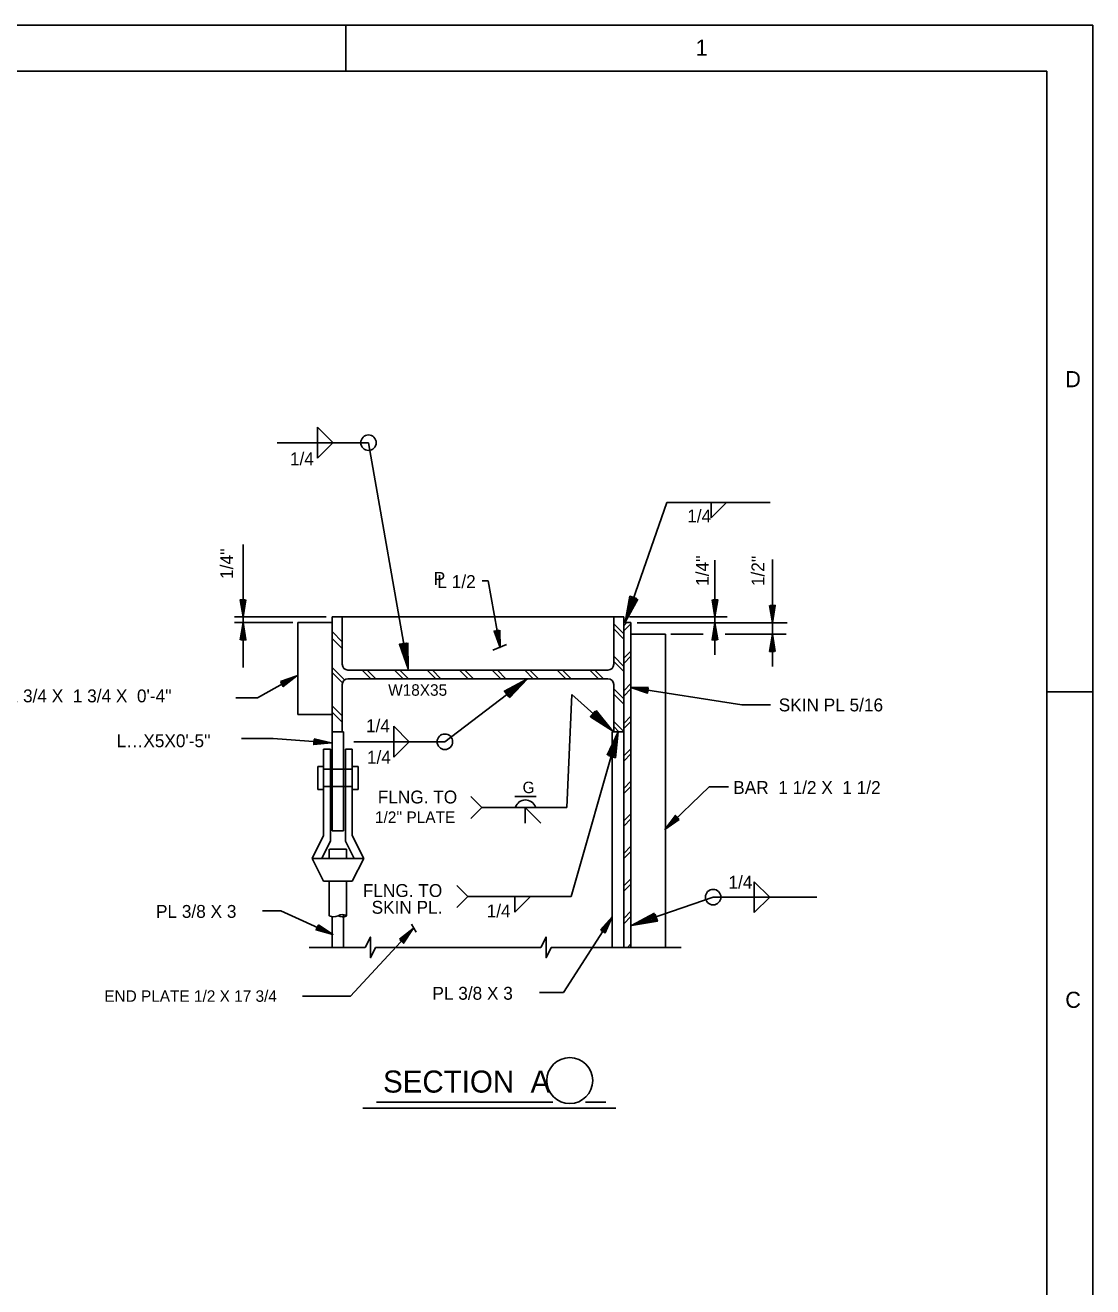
# Model space of a CAD drawing. Extents: x 0 to 13.3, y 0 to 9.3.
# Drawn here: x 9.463 to 13.333, y 4.76 to 9.333 of the extents above; entities that cross this region are included whole.
import ezdxf

# ---------------------------------------------------------------- set-up
doc = ezdxf.new("R2010")
doc.units = 0
for name, color, linetype in [('Level 1', 7, 'Continuous'), ('Level 10', 7, 'Continuous'), ('Level 13', 7, 'Continuous'), ('Level 2', 7, 'Continuous'), ('Level 25', 7, 'Continuous'), ('Level 3', 7, 'Continuous'), ('Level 50', 7, 'Continuous'), ('Level 7', 7, 'Continuous')]:
    doc.layers.add(name, color=color, linetype=linetype)

msp = doc.modelspace()

# ---------------------------------------------------------------- linework, layer by layer
at = {"layer": 'Level 1'}
for p, q in [((10.625, 9.1667), (10.625, 9.3333)), ((13.1667, 6.9167), (13.3333, 6.9167)), ((10.6955, 5.9903), (10.4927, 5.9903))]:
    msp.add_line(p, q, dxfattribs=at)
for points in [[(0, 9.3333), (13.3333, 9.3333), (13.3333, 0), (0, 0)], [(0.5, 9.1667), (13.1667, 9.1667), (13.1667, 0.1667), (0.5, 0.1667)]]:
    msp.add_lwpolyline(points, close=True, dxfattribs=at)
at = {"layer": 'Level 10'}
for points in [[(11.6329, 7.127), (11.5964, 7.1634)], [(11.6329, 7.1081), (11.5964, 7.1446)], [(11.6442, 7.1676), (11.6328, 7.1562)], [(11.6589, 7.1634), (11.6328, 7.1373)], [(10.6121, 7.0737), (10.5749, 7.111)], [(10.612, 7.098), (10.5762, 7.1338)], [(11.6329, 7.009), (11.5964, 7.0455)], [(11.6589, 7.0643), (11.6328, 7.0383)], [(11.6589, 7.0455), (11.6328, 7.0194)], [(10.6204, 6.9603), (10.5756, 7.0051)], [(11.6329, 6.9902), (11.5964, 7.0267)], [(10.6128, 6.949), (10.5756, 6.9863)], [(10.7153, 6.9644), (10.6841, 6.9957)], [(10.7342, 6.9644), (10.7029, 6.9957)], [(10.8332, 6.9644), (10.802, 6.9957)], [(10.8521, 6.9644), (10.8208, 6.9957)], [(10.9511, 6.9644), (10.9199, 6.9957)], [(10.97, 6.9644), (10.9388, 6.9957)], [(11.069, 6.9644), (11.0378, 6.9957)], [(11.0879, 6.9644), (11.0567, 6.9956)], [(11.187, 6.9644), (11.1557, 6.9957)], [(11.2058, 6.9644), (11.1746, 6.9957)], [(11.3049, 6.9644), (11.2736, 6.9957)], [(11.3238, 6.9644), (11.2925, 6.9957)], [(11.4228, 6.9644), (11.3915, 6.9957)], [(11.4416, 6.9644), (11.4104, 6.9957)], [(11.5407, 6.9644), (11.5094, 6.9957)], [(11.5595, 6.9644), (11.5283, 6.9957)], [(11.6329, 6.8911), (11.5964, 6.9276)], [(11.6329, 6.8723), (11.5964, 6.9088)], [(11.6589, 6.9464), (11.6328, 6.9204)], [(11.6589, 6.9275), (11.6328, 6.9015)], [(10.6128, 6.8282), (10.5756, 6.8655)], [(10.6121, 6.8067), (10.5749, 6.8439)], [(11.6589, 6.8285), (11.6328, 6.8024)], [(11.6329, 6.7732), (11.5964, 6.8097)], [(11.6155, 6.7717), (11.5964, 6.7908)], [(11.6589, 6.8096), (11.6328, 6.7836)], [(11.6589, 6.7106), (11.6328, 6.6845)], [(11.6589, 6.6917), (11.6328, 6.6656)], [(11.6589, 6.5927), (11.6329, 6.5666)], [(11.6589, 6.5738), (11.6329, 6.5478)], [(11.6589, 6.4748), (11.6329, 6.4487)], [(11.6589, 6.4559), (11.6329, 6.4299)], [(11.6589, 6.3569), (11.6329, 6.3308)], [(11.6589, 6.338), (11.6329, 6.312)], [(11.6589, 6.239), (11.6329, 6.2129)], [(11.6589, 6.2201), (11.6329, 6.194)], [(11.6589, 6.1211), (11.6329, 6.095)], [(11.6589, 6.1022), (11.6329, 6.0761)], [(11.6589, 6.0031), (11.6461, 5.9903)]]:
    msp.add_lwpolyline(points, dxfattribs=at)
at = {"layer": 'Level 13'}
for points in [[(10.6955, 5.9903), (10.7141, 6.0278), (10.7141, 5.9529), (10.7329, 5.9903)], [(11.3323, 5.9903), (11.351, 6.0278), (11.351, 5.9529), (11.3697, 5.9903)]]:
    msp.add_lwpolyline(points, dxfattribs=at)
for centre, radius, start, end in [((10.5802, 6.1384), 0.0372, 246.169, 296.6071), ((10.6135, 6.072), 0.0372, 69.8064, 116.6071), ((10.6135, 6.1384), 0.0372, 243.3929, 290.1936), ((10.6257, 6.1052), 0.00182, 290.1936, 69.8064)]:
    msp.add_arc(centre, radius, start, end, dxfattribs=at)
at = {"layer": 'Level 2'}
for p, q in [((10.5756, 6.7717), (10.5756, 7.1884)), ((10.612, 7.0165), (10.612, 7.1884)), ((10.612, 7.1884), (11.5964, 7.1884)), ((11.5964, 7.0165), (11.5964, 7.1884)), ((11.6329, 5.9903), (11.6329, 7.1884)), ((10.4506, 6.8342), (10.4506, 7.1676)), ((11.6589, 5.9903), (11.6589, 7.1676)), ((12.2248, 7.1675), (11.682, 7.1675)), ((11.784, 5.9903), (11.784, 7.1259)), ((11.9208, 7.1259), (11.8029, 7.1259)), ((12.2216, 7.1259), (12.0008, 7.1259)), ((11.5755, 6.9957), (10.6329, 6.9957)), ((11.5755, 6.9644), (10.6329, 6.9644)), ((11.1251, 6.9957), (11.0834, 6.9957)), ((10.612, 6.7717), (10.612, 6.9436)), ((11.5964, 6.7717), (11.5964, 6.9436)), ((10.5756, 6.4124), (10.5756, 6.7717)), ((10.6172, 6.4124), (10.6172, 6.7717)), ((11.5912, 5.9903), (11.5912, 6.7717)), ((10.5443, 6.3965), (10.5443, 6.7092)), ((10.5692, 6.7092), (10.5443, 6.7092)), ((10.5692, 6.3765), (10.5692, 6.7092)), ((10.624, 6.3757), (10.624, 6.7092)), ((10.6485, 6.7092), (10.624, 6.7092)), ((10.6485, 6.3965), (10.6485, 6.7092)), ((10.5234, 6.5633), (10.5234, 6.6466)), ((10.5443, 6.6466), (10.5234, 6.6466)), ((10.6485, 6.6362), (10.5443, 6.6362)), ((10.6693, 6.6466), (10.6485, 6.6466)), ((10.6693, 6.5633), (10.6693, 6.6466)), ((10.5443, 6.5633), (10.5234, 6.5633)), ((10.6485, 6.5737), (10.5443, 6.5737)), ((10.6693, 6.5633), (10.6485, 6.5633)), ((10.5443, 6.3965), (10.5026, 6.3131)), ((10.5692, 6.3765), (10.5376, 6.3131)), ((10.624, 6.3757), (10.6553, 6.3131)), ((10.6485, 6.3965), (10.6902, 6.3131)), ((10.6902, 6.3131), (10.5026, 6.3131)), ((10.5026, 6.3131), (10.5443, 6.2298)), ((10.5651, 6.3131), (10.5651, 6.3468)), ((10.6277, 6.3468), (10.5664, 6.3468)), ((10.6277, 6.3131), (10.6277, 6.3468)), ((10.6902, 6.3131), (10.6485, 6.2298)), ((10.6485, 6.2298), (10.5443, 6.2298)), ((10.5651, 6.1044), (10.5651, 6.2298)), ((10.6277, 6.1051), (10.6277, 6.2298)), ((10.5756, 5.9903), (10.5756, 6.1015)), ((10.6172, 5.9903), (10.6172, 6.109)), ((11.3323, 5.9903), (10.7329, 5.9903)), ((11.8414, 5.9903), (11.3697, 5.9903))]:
    msp.add_line(p, q, dxfattribs=at)
at = {"layer": 'Level 25'}
for p, q in [((11.7889, 7.6036), (11.6385, 7.1699)), ((11.647, 7.1945), (11.647, 7.1945)), ((11.6385, 7.1699), (11.6385, 7.1699)), ((10.8463, 7.0252), (10.8463, 7.0252)), ((10.8508, 6.9996), (10.8508, 6.9996)), ((11.4424, 6.1745), (11.6131, 6.7723)), ((11.5724, 6.7928), (11.5724, 6.7928)), ((11.5918, 6.7754), (11.5918, 6.7754)), ((11.6131, 6.7723), (11.6131, 6.7723)), ((11.606, 6.7473), (11.606, 6.7473)), ((11.1185, 6.4972), (11.0787, 6.5371)), ((11.1185, 6.4972), (11.0787, 6.4575)), ((11.4262, 6.4972), (11.1185, 6.4972)), ((11.2757, 6.4972), (11.2757, 6.441)), ((11.2757, 6.4972), (11.3317, 6.4412))]:
    msp.add_line(p, q, dxfattribs=at)
for points in [[(11.6838, 7.2532), (11.6385, 7.1699), (11.6545, 7.2633), (11.6796, 7.2546), (11.647, 7.1945), (11.6579, 7.2579), (11.674, 7.2523), (11.6552, 7.2181), (11.6613, 7.2525), (11.6679, 7.2502), (11.6638, 7.2426)], [(10.8499, 7.0943), (10.8508, 6.9996), (10.8194, 7.089), (10.8455, 7.0936), (10.8463, 7.0252), (10.825, 7.0859), (10.8417, 7.0888), (10.842, 7.0498), (10.8306, 7.0828), (10.8375, 7.084), (10.8375, 7.0754)], [(11.5325, 6.8494), (11.5918, 6.7754), (11.5118, 6.8263), (11.5295, 6.8461), (11.5724, 6.7928), (11.5181, 6.8274), (11.5295, 6.84), (11.5538, 6.8095), (11.5245, 6.8284), (11.5291, 6.8336), (11.5345, 6.8268)], [(11.5725, 6.6866), (11.6131, 6.7723), (11.6023, 6.6781), (11.5769, 6.6854), (11.606, 6.7473), (11.5986, 6.6833), (11.5823, 6.688), (11.5991, 6.7232), (11.5949, 6.6885), (11.5882, 6.6905), (11.592, 6.6982)]]:
    msp.add_lwpolyline(points, dxfattribs=at)
at = {"layer": 'Level 3'}
for p, q in [((10.2528, 7.1884), (10.2528, 7.4505)), ((11.9632, 7.1884), (11.9632, 7.3939)), ((12.1716, 7.1675), (12.1716, 7.397)), ((10.5537, 7.1884), (10.2215, 7.1884)), ((10.2528, 7.1676), (10.2528, 7.1884)), ((12.0072, 7.1884), (11.6531, 7.1884)), ((11.9632, 7.2057), (11.9632, 7.2057)), ((11.9632, 7.1443), (11.9632, 7.2051)), ((11.9632, 7.1884), (11.9632, 7.1884)), ((12.1716, 7.1059), (12.1716, 7.1955)), ((12.1716, 7.1849), (12.1716, 7.1849)), ((10.4331, 7.1676), (10.2213, 7.1676)), ((10.2528, 7.0055), (10.2528, 7.1676)), ((11.9632, 7.1675), (11.9632, 7.1675)), ((11.9632, 7.0505), (11.9632, 7.1675)), ((11.9632, 7.1502), (11.9632, 7.1502)), ((12.1716, 7.1675), (12.1716, 7.1675)), ((11.181, 7.0944), (11.181, 7.0944)), ((12.1716, 7.1259), (12.1716, 7.1259)), ((12.1716, 7.009), (12.1716, 7.1259)), ((12.1716, 7.1085), (12.1716, 7.1085)), ((11.1582, 7.0683), (11.2075, 7.088)), ((11.1841, 7.0773), (11.1841, 7.0773)), ((10.4322, 6.9668), (10.4322, 6.9668)), ((10.4473, 6.9753), (10.4473, 6.9753)), ((11.2839, 6.964), (11.2839, 6.964)), ((11.2633, 6.9481), (11.2633, 6.9481)), ((11.6589, 6.932), (12.061, 6.8702)), ((11.6589, 6.932), (11.6589, 6.932)), ((11.6761, 6.9294), (11.6761, 6.9294)), ((12.1649, 6.8702), (12.061, 6.8702)), ((10.5543, 6.7326), (10.5543, 6.7326)), ((10.5716, 6.7313), (10.5716, 6.7313)), ((11.7822, 6.4181), (11.7822, 6.4181)), ((11.7947, 6.4301), (11.7947, 6.4301)), ((11.581, 6.0859), (11.581, 6.0859)), ((11.5904, 6.1005), (11.5904, 6.1005)), ((10.5627, 6.0445), (10.5627, 6.0445)), ((10.5785, 6.0374), (10.5785, 6.0374)), ((10.8574, 6.0456), (10.8574, 6.0456)), ((10.8692, 6.0583), (10.8692, 6.0583)), ((11.6614, 6.0691), (11.6614, 6.0691)), ((11.686, 6.0776), (11.686, 6.0776)), ((10.6864, 5.408), (11.6044, 5.408)), ((10.7364, 5.4288), (11.3762, 5.4288)), ((11.5675, 5.4288), (11.4945, 5.4288))]:
    msp.add_line(p, q, dxfattribs=at)
for points in [[(11.1196, 7.3191), (11.1408, 7.3191), (11.1841, 7.0773)], [(11.9529, 7.2508), (11.9632, 7.1884), (11.9735, 7.2508), (11.9559, 7.2508), (11.9632, 7.2057), (11.9702, 7.2481), (11.9589, 7.2481), (11.9632, 7.2224), (11.9669, 7.2454), (11.9622, 7.2454), (11.9632, 7.2398)], [(12.1613, 7.2299), (12.1716, 7.1675), (12.182, 7.2299), (12.1643, 7.2299), (12.1716, 7.1849), (12.1786, 7.2272), (12.1673, 7.2272), (12.1716, 7.2016), (12.1753, 7.2246), (12.1706, 7.2246), (12.1716, 7.2189)], [(11.1832, 7.1405), (11.1841, 7.0773), (11.1629, 7.1369), (11.1803, 7.14), (11.181, 7.0944), (11.1666, 7.1348), (11.1778, 7.1368), (11.1781, 7.1108), (11.1704, 7.1328), (11.175, 7.1336), (11.175, 7.1279)], [(11.9735, 7.1052), (11.9632, 7.1675), (11.9529, 7.1052), (11.9705, 7.1052), (11.9632, 7.1502), (11.9562, 7.1079), (11.9675, 7.1079), (11.9632, 7.1335), (11.9595, 7.1105), (11.9642, 7.1105), (11.9632, 7.1162)], [(12.182, 7.0635), (12.1716, 7.1259), (12.1613, 7.0635), (12.179, 7.0635), (12.1716, 7.1085), (12.1646, 7.0662), (12.176, 7.0662), (12.1716, 7.0918), (12.168, 7.0688), (12.1726, 7.0688), (12.1716, 7.0745)], [(10.2263, 6.8947), (10.3046, 6.8947), (10.4473, 6.9753)], [(10.3879, 6.9537), (10.4473, 6.9753), (10.3981, 6.9357), (10.3894, 6.9511), (10.4322, 6.9668), (10.3988, 6.9399), (10.3932, 6.9498), (10.4177, 6.9586), (10.3994, 6.9441), (10.3972, 6.9482), (10.4026, 6.9501)], [(11.219, 6.8948), (11.2839, 6.964), (11.2002, 6.9194), (11.2163, 6.8984), (11.2633, 6.9481), (11.2064, 6.9179), (11.2168, 6.9044), (11.2434, 6.9329), (11.2126, 6.9164), (11.2169, 6.9108), (11.2227, 6.9172)], [(11.7221, 6.9328), (11.6589, 6.932), (11.719, 6.9124), (11.7217, 6.9298), (11.6761, 6.9294), (11.7169, 6.916), (11.7186, 6.9272), (11.6926, 6.9269), (11.7147, 6.9197), (11.7154, 6.9244), (11.7097, 6.9242)], [(10.247, 6.747), (10.3621, 6.747), (10.5716, 6.7313)], [(10.5102, 6.7463), (10.5716, 6.7313), (10.5086, 6.7257), (10.51, 6.7433), (10.5543, 6.7326), (10.5116, 6.7288), (10.5124, 6.7401), (10.5377, 6.7339), (10.5145, 6.7319), (10.5148, 6.7366), (10.5204, 6.7352)], [(12.0126, 6.5723), (11.9425, 6.5723), (11.7822, 6.4181)], [(11.8343, 6.4539), (11.7822, 6.4181), (11.82, 6.4688), (11.8322, 6.456), (11.7947, 6.4301), (11.8204, 6.4645), (11.8282, 6.4564), (11.8067, 6.4417), (11.8208, 6.4603), (11.824, 6.4569), (11.8192, 6.4537)], [(10.323, 6.1224), (10.3897, 6.1224), (10.5785, 6.0374)], [(11.3273, 5.827), (11.4143, 5.827), (11.5904, 6.1005)], [(11.548, 6.0537), (11.5904, 6.1005), (11.5653, 6.0425), (11.5505, 6.052), (11.581, 6.0859), (11.564, 6.0465), (11.5545, 6.0527), (11.572, 6.0719), (11.5626, 6.0506), (11.5587, 6.0531), (11.5626, 6.0573)], [(11.7448, 6.1142), (11.6614, 6.0691), (11.7549, 6.0849), (11.7463, 6.11), (11.686, 6.0776), (11.7495, 6.0883), (11.744, 6.1044), (11.7097, 6.0857), (11.7441, 6.0918), (11.7418, 6.0983), (11.7343, 6.0942)], [(10.4683, 5.8136), (10.6415, 5.8136), (10.8692, 6.0583)], [(10.5259, 6.0724), (10.5785, 6.0374), (10.5174, 6.0536), (10.5247, 6.0697), (10.5627, 6.0445), (10.5212, 6.0555), (10.5259, 6.0659), (10.5475, 6.0514), (10.525, 6.0575), (10.5269, 6.0617), (10.5317, 6.0585)], [(10.8192, 6.0197), (10.8692, 6.0583), (10.8343, 6.0056), (10.8214, 6.0177), (10.8574, 6.0456), (10.8337, 6.0098), (10.8254, 6.0176), (10.8461, 6.0334), (10.8331, 6.0141), (10.8297, 6.0172), (10.8343, 6.0207)]]:
    msp.add_lwpolyline(points, dxfattribs=at)
msp.add_circle((11.4369, 5.5076), 0.0833, dxfattribs=at)
for centre, start, end in [((10.6329, 7.0165), 180, 270), ((11.5755, 7.0165), 270, 0), ((10.6329, 6.9436), 90, 180), ((11.5755, 6.9436), 0, 90)]:
    msp.add_arc(centre, 0.0208, start, end, dxfattribs=at)
at = {"layer": 'Level 50'}
for p, q in [((10.7073, 7.8199), (10.8508, 6.9996)), ((10.2528, 7.2057), (10.2528, 7.2057)), ((10.2528, 7.1884), (10.2528, 7.1884)), ((10.612, 7.1884), (10.5756, 7.1884)), ((11.6329, 7.1884), (11.5964, 7.1884)), ((10.2528, 7.1676), (10.2528, 7.1676)), ((10.2528, 7.1502), (10.2528, 7.1502)), ((10.4506, 7.1676), (10.5756, 7.1676)), ((11.6589, 7.1676), (11.6329, 7.1676)), ((11.784, 7.1259), (11.6589, 7.1259)), ((11.4262, 6.4972), (11.4444, 6.9077)), ((11.4444, 6.9077), (11.5918, 6.7754)), ((10.4506, 6.8342), (10.5756, 6.8342)), ((10.6172, 6.7717), (10.5756, 6.7717)), ((11.6329, 6.7717), (11.5912, 6.7717)), ((11.238, 6.5375), (11.3155, 6.5375)), ((10.5756, 6.4124), (10.6172, 6.4124)), ((10.8629, 6.074), (10.8797, 6.0457))]:
    msp.add_line(p, q, dxfattribs=at)
for points in [[(10.2631, 7.2507), (10.2528, 7.1884), (10.2425, 7.2507), (10.2601, 7.2507), (10.2528, 7.2057), (10.2458, 7.2481), (10.2571, 7.2481), (10.2528, 7.2224), (10.2491, 7.2454), (10.2538, 7.2454), (10.2528, 7.2397)], [(10.2425, 7.1052), (10.2528, 7.1676), (10.2631, 7.1052), (10.2455, 7.1052), (10.2528, 7.1502), (10.2598, 7.1079), (10.2485, 7.1079), (10.2528, 7.1336), (10.2565, 7.1106), (10.2518, 7.1106), (10.2528, 7.1162)]]:
    msp.add_lwpolyline(points, dxfattribs=at)
msp.add_arc((11.2765, 6.4864), 0.0383, 20.1021, 161.1053, dxfattribs=at)
at = {"layer": 'Level 7'}
for p, q in [((10.5221, 7.8762), (10.578, 7.8203)), ((10.5221, 7.8199), (10.5221, 7.8762)), ((10.7073, 7.8199), (10.3767, 7.8199)), ((10.5221, 7.8199), (10.5221, 7.7636)), ((10.5221, 7.7636), (10.578, 7.8195)), ((12.1642, 7.6036), (11.7889, 7.6036)), ((11.9492, 7.6036), (11.9492, 7.5474)), ((11.9492, 7.5474), (12.0051, 7.6033)), ((11.2833, 6.9644), (10.9842, 6.7358)), ((10.799, 6.792), (10.8549, 6.7361)), ((10.799, 6.7358), (10.799, 6.792)), ((10.9842, 6.7358), (10.6536, 6.7358)), ((10.799, 6.7358), (10.799, 6.6795)), ((10.799, 6.6795), (10.8549, 6.7354)), ((12.106, 6.2283), (12.1619, 6.1724)), ((12.106, 6.172), (12.106, 6.2283)), ((11.0672, 6.1745), (11.0273, 6.2144)), ((11.0672, 6.1745), (11.0273, 6.1348)), ((11.4424, 6.1745), (11.0672, 6.1745)), ((11.2373, 6.1745), (11.2373, 6.1183)), ((11.2373, 6.1183), (11.2932, 6.1742)), ((11.6589, 6.0701), (11.9569, 6.1726)), ((11.9569, 6.1726), (12.3323, 6.1726)), ((12.106, 6.1731), (12.106, 6.1169)), ((12.106, 6.1169), (12.1619, 6.1728))]:
    msp.add_line(p, q, dxfattribs=at)
for centre in [(10.7073, 7.8199), (10.9842, 6.7358), (11.9569, 6.1726)]:
    msp.add_circle(centre, 0.0281, dxfattribs=at)

# ---------------------------------------------------------------- texts
at = {"layer": 'Level 1'}
for s, p in [('1', (11.8936, 9.223)), ('D', (13.2337, 8.0211)), ('C', (13.2337, 5.7711))]:
    msp.add_text(s, height=0.0584, dxfattribs=at).set_placement(p)
at = {"layer": 'Level 3'}
for s, height, p in [('1/4', 0.04669, (10.4224, 7.738)), ('1/4', 0.04669, (11.8631, 7.5308)), ('P', 0.0467, (10.9438, 7.3044)), ('L 1/2', 0.0467, (10.9571, 7.2931)), ("BAR  1 3/4 X  1 3/4 X  0'-4''", 0.046688, (9.2396, 6.8787)), ('SKIN PL 5/16', 0.04669, (12.1947, 6.8459)), ('1/4', 0.04669, (10.6982, 6.7704)), ("L…X5X0'-5''", 0.046677, (9.7938, 6.716)), ('1/4', 0.04669, (10.7017, 6.6563)), ('BAR  1 1/2 X  1 1/2', 0.04669, (12.0298, 6.5466)), ('FLNG. TO', 0.04669, (10.7409, 6.5121)), ('FLNG. TO', 0.04669, (10.6868, 6.1731)), ('1/4', 0.04669, (12.0125, 6.2033)), ('PL 3/8 X 3', 0.04669, (9.9368, 6.0974)), ('SKIN PL.', 0.04669, (10.7186, 6.1123)), ('1/4', 0.04669, (11.1359, 6.0991)), ('PL 3/8 X 3', 0.04669, (10.939, 5.8006)), ('SECTION  A', 0.08, (10.7601, 5.4639))]:
    msp.add_text(s, height=height, dxfattribs=at).set_placement(p)
for s, p in [("1/4''", (10.2165, 7.3261)), ("1/4''", (11.9412, 7.3009)), ("1/2''", (12.1427, 7.3))]:
    msp.add_text(s, height=0.04669, rotation=90, dxfattribs=at).set_placement(p)
at = {"layer": 'Level 50'}
for s, height, p in [('W18X35', 0.0417, (10.7786, 6.9025)), ('G', 0.0417, (11.266, 6.5494)), ("1/2'' PLATE", 0.041698, (10.7308, 6.4414)), ('END PLATE 1/2 X 17 3/4', 0.041698, (9.7492, 5.793))]:
    msp.add_text(s, height=height, dxfattribs=at).set_placement(p)

doc.saveas('drawing.dxf')
